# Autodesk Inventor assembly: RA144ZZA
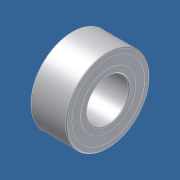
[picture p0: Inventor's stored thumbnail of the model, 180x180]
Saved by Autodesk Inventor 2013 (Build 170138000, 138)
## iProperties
Category: PARTsolutions
Created: 2011-07
Part Number: RA144ZZA
Catalog Web Link: www.cadenas.de
Description: With double shield ZZ -
Document SubType Name: Assembly
Designer: PARTsolutions
NB: RA144ZZA
NN: With double shield ZZ
NBSYN: RA144ZZA
LINA: RA144ZZA
PSOL_MULTISOLIDPART: 0.0
SD: 3.175
D: 6.350
B: 2.380
B1: 2.779
D1: 7.52
D2: 7.52
C1: 0.58
C2: 0.79
R: 0.08
ORDER: RA144ZZA
CR: 284
COR: 96
CRF: 29
CORF: 10
LSG: 59000
LSO: 70000
MASS: 0.27
ORDER1: R144
WSS: RA144ZA
WDS: RA144ZZA
UTWF: FLR144
FORSS: FLRA144ZA
FORDS: FLRA144ZZA
DA1: 3.9
DA2: 4
DA: 5.5
RAS: 0.08
MASS1: 0.33
VERS: 3
X: 1.587
N: 9
O: 14.954
RB: 0.470
PPATH: iss_asmtpl.prj
KT: DUMMY
CreationOption_UseAsmMates: 0
SUPPLIER: NTN
ARTICLENO: RA144ZZA
BOMINFO: RA144ZZA
CREATOR: CADENAS GmbH
PSOL_IDENT_0: {\\10.0.0.251\ps_data\23d-libs\ntn\ball_roller_bearings\miniature_extra_small_bb\inch_system_sizes\i
PSOL_IDENT_1: ss_zz_asmtab.prj},181 {VTYP=3D},{STYP=ASSTAB},{NB=RA144ZZA},{LINA=RA144ZZA},{NN=With double shield Z
PSOL_IDENT_2: Z},{DATE=11.12.2007 08:48:22},{GEOMDATE=02.04.2007},{VERSION=},{LINEID=16080},{LINESUBID=-1},{WBVAR=
PSOL_IDENT_3: }  {NB=RA144ZZA},{LINA=RA144ZZA},{KT=DUMMY},{IDNR=},{SD=3.175},{D=6.350},{B=2.380},{B1=2.779},{D1=7.
PSOL_IDENT_4: 52},{D2=7.52},{C1=0.58},{C2=0.79},{R=0.08},{ORDER=RA144ZZA},{CR=284},{COR=96},{CRF=29},{CORF=10},{LS
PSOL_IDENT_5: G=59000},{LSO=70000},{MASS=0.27},{ORDER1=R144},{WSS=RA144ZA},{WDS=RA144ZZA},{UTWF=FLR144},{FORSS=FLR
PSOL_IDENT_6: A144ZA},{FORDS=FLRA144ZZA},{DA1=3.9},{DA2=4},{DA=5.5},{RAS=0.08},{MASS1=0.33},{VERS=3},{X=1.5875},{N
PSOL_IDENT_7: =9},{O=14.95425},{RB=0.4699},{PPATH=iss_asmtpl.prj}
Title: RA144ZZA
Author: Cadenas PARTsolutions
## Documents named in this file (5)
- D:\_an13-14\FORMULAIRE_2014\Sujet E4 Poissy 2014\Modélisation_7970_shimano_2014\éléments standards\PARTserver35516212\RA144ZZA.iam
- D:\_an13-14\FORMULAIRE_2014\Sujet E4 Poissy 2014\Modélisation_7970_shimano_2014\éléments standards\PARTserver35516212\RA144ZZA_Inner_ring.ipt
- D:\_an13-14\FORMULAIRE_2014\Sujet E4 Poissy 2014\Modélisation_7970_shimano_2014\éléments standards\PARTserver35516212\RA144ZZA_Outer_ring.ipt
- D:\_an13-14\FORMULAIRE_2014\Sujet E4 Poissy 2014\Modélisation_7970_shimano_2014\éléments standards\PARTserver35516212\RA144ZZA_Shield.ipt
- D:\_an13-14\FORMULAIRE_2014\Sujet E4 Poissy 2014\Modélisation_7970_shimano_2014\éléments standards\PARTserver35516212\RA144ZZA_Ball.ipt
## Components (13 placed, 4 different names)
1. RA144ZZA Inner ring:1
2. RA144ZZA Outer ring:1
3. RA144ZZA Shield:1
4. RA144ZZA Shield:2
5. RA144ZZA Ball:1
6. RA144ZZA Ball:2
7. RA144ZZA Ball:3
8. RA144ZZA Ball:4
9. RA144ZZA Ball:5
10. RA144ZZA Ball:6
11. RA144ZZA Ball:7
12. RA144ZZA Ball:8
13. RA144ZZA Ball:9
